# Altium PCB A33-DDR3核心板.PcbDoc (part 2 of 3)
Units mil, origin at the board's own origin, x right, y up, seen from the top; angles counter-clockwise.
Board outline 2370 x 2515 mil, 4 copper layers (TOP, GND02, PWR03, BOTTOM), stack 38.4 mil thick; 39 components, 64 nets, 546 pads, 403 vias.
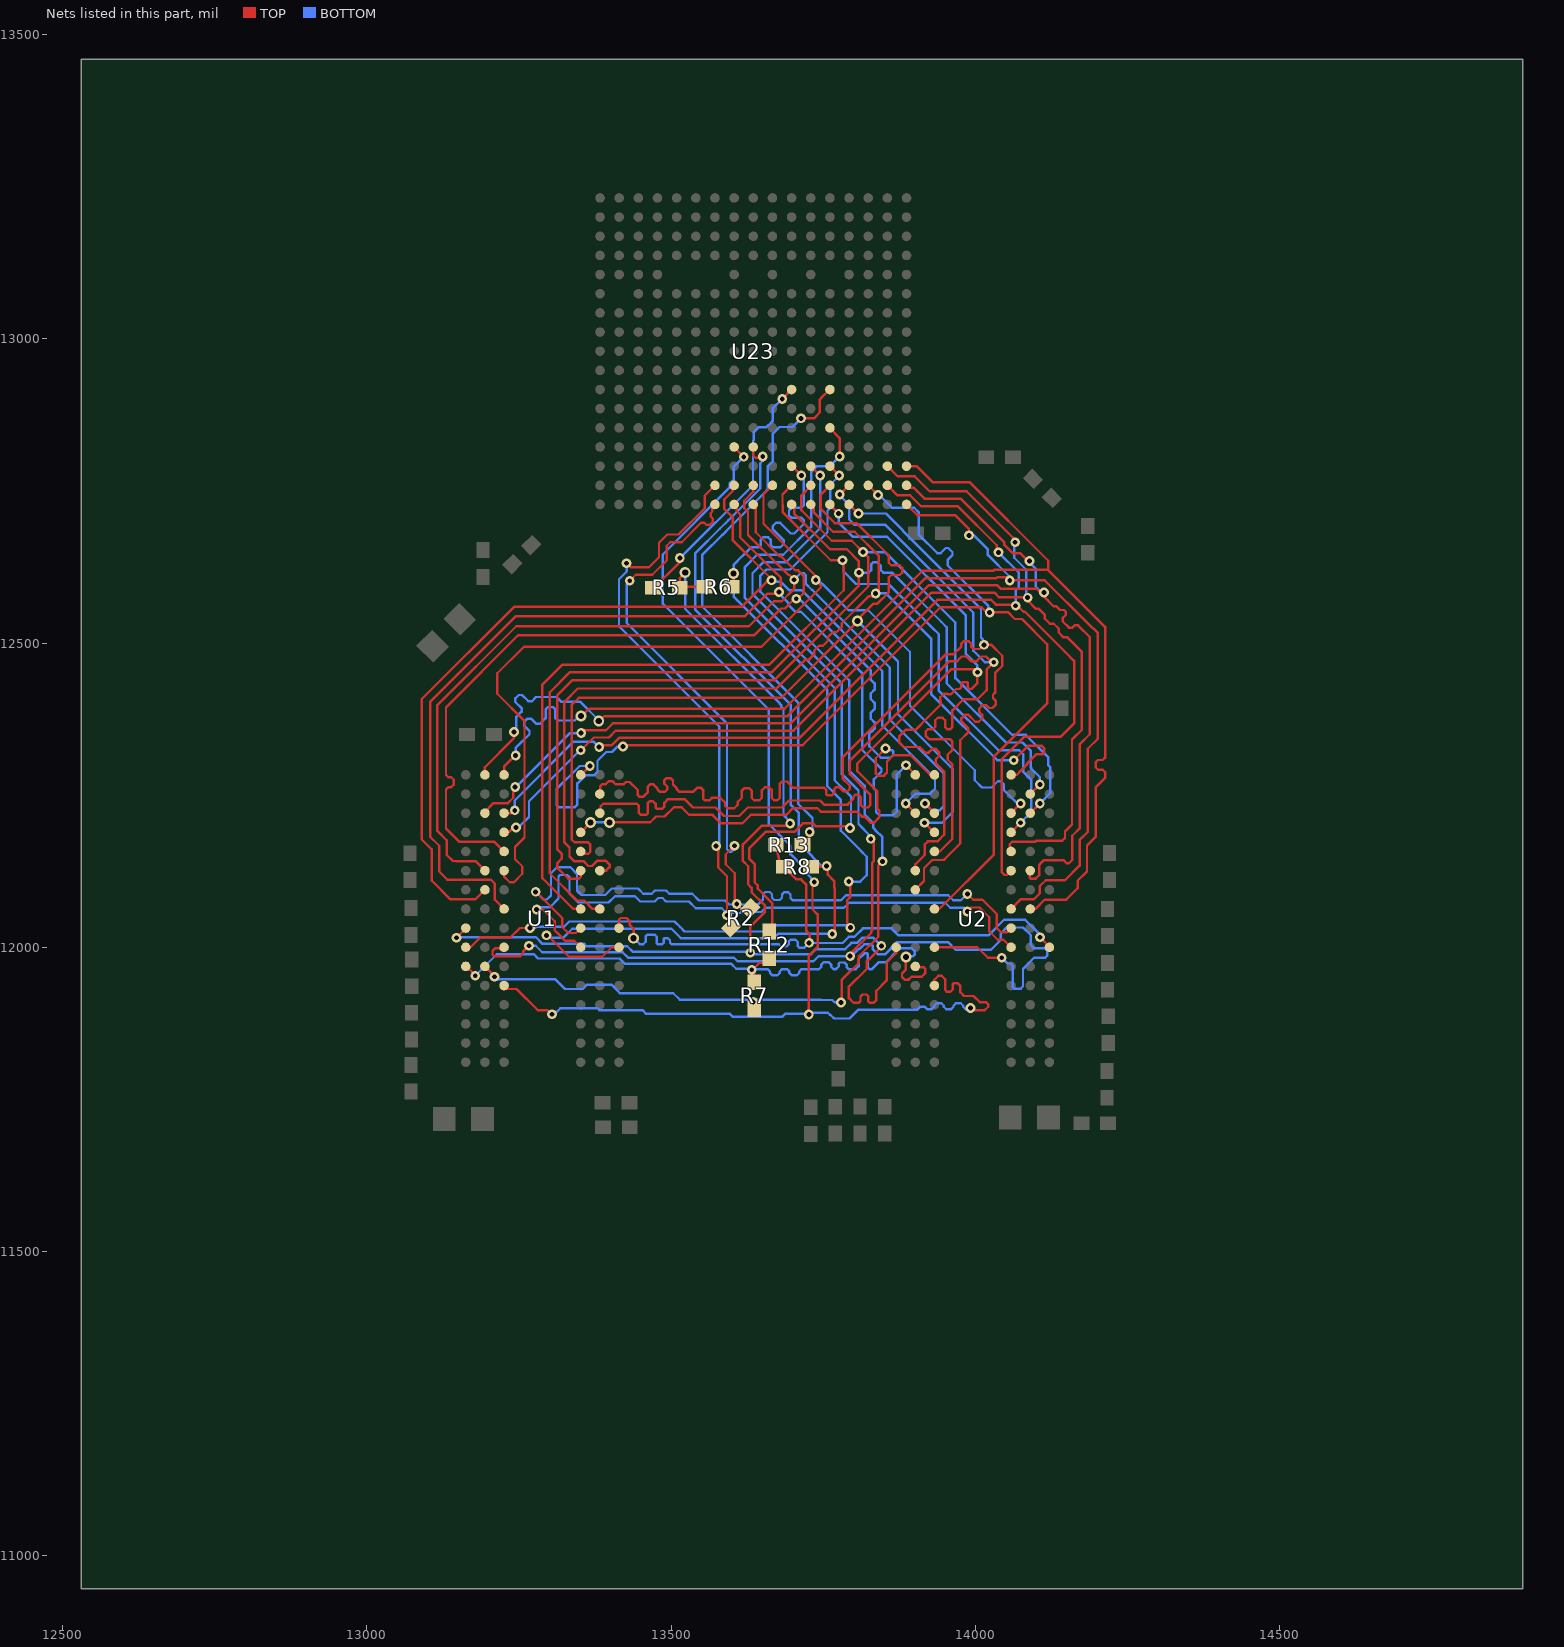
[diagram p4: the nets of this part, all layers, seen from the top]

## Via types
v1: diameter 16, hole 8, TOP to BOTTOM, 320 vias
v2: diameter 18, hole 10, TOP to BOTTOM, 83 vias

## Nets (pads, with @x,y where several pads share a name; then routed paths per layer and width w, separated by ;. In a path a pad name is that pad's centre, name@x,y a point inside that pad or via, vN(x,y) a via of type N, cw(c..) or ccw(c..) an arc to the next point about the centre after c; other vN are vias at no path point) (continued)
DBA2: U1.M3 U2.M3 U23.H4 | length 2134.1
  TOP w4: U1.M3@13225.38,11936.86 13231.01,11931.23 13246.06,11931.23 13280.9,11896.39 13296.38,11896.39 13303.1,11889.66 v1(13304.13,11889.66) ; U23.H4@13603.56,12822.31 13603.56,12821.96 v1(13619.44,12806.12) ; v1(13726.48,11889.19) 13726.48,11986.07 13740.93,12000.52 13740.93,12053.88 13732.44,12062.37 13732.44,12104.01 v1(13735.34,12106.91) ; U2.M3@13932.93,11936.85 13932.93,11946.4 13939.22,11952.69 13944.92,11952.69 13950.59,11947.01 13950.59,11929.56 13953.42,11926.73 13959.08,11926.73 13962.9,11930.55 13962.9,11938.95 13964.99,11941.04 13970.96,11941.04 13975.59,11936.41 13975.59,11925.8 13981.61,11919.78 13997.24,11919.78 14007.59,11909.43 14017.86,11909.43 14021.39,11905.89 14021.39,11902.09 14015.72,11896.41 13995.99,11896.41 v1(13992.24,11900.17)
  BOTTOM w4: v1(13304.13,11889.66) 13307.49,11889.66 13308.07,11890.24 13308.4,11890.24 13317.83,11899.67 13378.96,11899.67 13382.13,11896.5 13452.71,11896.5 13458.37,11890.84 13596.1,11890.84 13601.11,11885.83 13683.14,11885.83 13688.09,11890.78 13724.89,11890.78 v1(13726.48,11889.19) 13729.55,11892.27 13757.57,11892.27 13760.69,11889.15 13761.45,11889.15 13766.56,11884.04 13767.07,11884.04 13768.39,11882.72 13793.19,11882.72 13807.45,11896.98 13904.35,11896.98 13909.78,11902.41 13916.48,11902.41 13920.74,11898.15 13928.25,11898.15 13932.25,11902.15 13932.25,11903.78 13936.25,11907.78 13944.25,11907.78 13948.25,11903.78 13948.25,11902.15 13952.25,11898.15 13960.25,11898.15 13964.25,11902.15 13964.25,11903.78 13968.25,11907.78 13976.25,11907.78 13980.25,11903.78 13980.25,11902.15 13984.25,11898.15 13989.45,11898.15 13989.83,11897.77 v1(13992.24,11900.17) ; v1(13619.44,12806.12) 13618.64,12805.32 13618.45,12805.32 13603.08,12789.96 13603.08,12769.13 13596.09,12762.14 13596.09,12755.51 13486.19,12645.61 13486.19,12564.77 13658.8,12392.17 13658.8,12391.78 13660.79,12389.79 13660.79,12202 13677.88,12184.92 13677.88,12184.86 13696.04,12166.7 13696.04,12153.1 13723.7,12125.44 13723.7,12120.47 13735.09,12109.08 13735.09,12107.16 v1(13735.34,12106.91)
DCAS: U1.K3 U2.K3 U23.M3 | length 2302.2
  TOP w4: U1.K3@13225.37,11999.84 13223.94,11998.41 13211.05,11998.41 13206.36,11993.72 13206.36,11988.07 13209.25,11985.18 13251.73,11985.18 13256.67,11990.11 13256.67,11992.65 v1(13266.36,12002.34) ; U23.M3@13729.55,12790.81 v1(13745.02,12775.34) ; v1(13794.34,11985.25) 13794.34,11986.6 13796.84,11989.1 13796.84,11991.14 13829.35,12023.65 13829.35,12026.55 13830.47,12027.67 13830.47,12138.74 13832.82,12141.09 13832.82,12173.55 v1(13828.24,12178.13) ; U2.K3@13932.93,11999.84 14003.35,11999.84 14020.68,11982.52 v1(14043.58,11982.52)
  BOTTOM w4: v1(13266.36,12002.34) 13277.48,12002.34 13288.23,11991.6 13388.64,11991.6 13411.3,11991.59 13411.47,11991.43 13420.49,11991.43 13429.11,11982.81 13599.06,11982.81 13599.35,11982.52 13603.38,11982.52 13609.07,11976.83 13734.11,11976.83 13742.67,11985.39 13794.2,11985.39 v1(13794.34,11985.25) 13795.1,11986.01 13797.09,11986.01 13808.12,11997.04 13809.78,11997.04 13811.49,11998.75 ; v1(13745.02,12775.34) 13745.02,12688.8 13689.35,12633.13 13652.08,12633.13 13633.76,12614.82 13633.76,12580.54 13780.79,12433.51 13780.79,12284.53 13808.01,12257.32 13808.01,12202.24 13828.24,12182.01 v1(13828.24,12178.13) ; 13811.53,11998.75 13817.66,12004.88 13828.82,12004.88 13831.64,12002.05 13831.64,11996.39 13839.84,11988.19 13851.44,11988.19 13871.55,12008.3 13955.04,12008.3 13967.88,11995.46 14025.39,11995.46 14041.95,12012.01 14041.95,12022.62 14051.63,12032.31 14078.77,12032.31 14091.21,12019.86 14091.21,12003.7 14096.85,11998.06 14115.29,11998.06 14118.11,11995.23 14118.11,11985.88 14115.16,11982.92 14097.08,11982.92 14078.53,11964.37 14078.53,11935.67 14074.53,11931.67 14064.03,11931.67 14061.96,11933.73 14061.96,11968.93 14057.73,11973.17 14052.94,11973.17 v1(14043.58,11982.52)
DCK: R2.1 U1.J7 U2.J7 U23.G1 | length 1985.9
  TOP w3.7: v1(13277.32,12090.91) 13279.03,12089.2 13279.84,12089.2 13321.2,12047.83 13321.2,12032.63 13330.66,12023.17 13343.18,12023.17 U1.J7@13351.35,12031.34 ; v1(13431.99,12602.36) 13441.71,12612.08 13468.99,12612.08 13492.76,12635.84 13492.76,12649.74 13492.76,12659.82 13498.73,12665.79 13517.47,12665.79 13549.3,12697.62 13554.53,12697.62 13557.74,12694.41 13563.78,12694.41 13568.28,12698.91 13568.28,12704.8 13564.99,12708.09 13564.99,12713.32 13567.79,12716.12 13567.79,12723.55 U23.G1@13572.07,12727.82 ; v1(13604.08,12166.8) 13589.84,12152.56 13589.84,12136.28 13604.51,12121.61 13604.51,12074.41 v1(13607.79,12071.14) 13615.09,12063.83 R2.1@13629.84,12063.83 ; v1(13987.03,12087.52) 13996.63,12077.92 14012.08,12077.92 14035.53,12054.47 14035.53,12031.34 14042.2,12024.67 14052.24,12024.67 U2.J7@14058.91,12031.34
  BOTTOM w3.7: v1(13277.32,12090.91) 13290.04,12078.18 13295.56,12078.18 13302.44,12085.06 13302.44,12121.34 13312.31,12131.21 13334.55,12131.21 13345.31,12120.45 13345.31,12093.2 13352.72,12085.79 13391.76,12085.79 13402.38,12096.41 13445.61,12096.41 13454.26,12087.76 13468.02,12087.76 13473.4,12093.14 13491.54,12093.14 13496.92,12087.76 13534.59,12087.76 13545.69,12076.67 13588.51,12076.67 13595.14,12070.04 13606.69,12070.04 v1(13607.79,12071.14) 13608.74,12070.19 13642.91,12070.19 13651.22,12078.5 13651.22,12086.97 13654.92,12090.67 13662.32,12090.67 13666.02,12086.97 13666.02,12081.37 13669.72,12077.67 13678.42,12077.67 13682.12,12081.37 13682.12,12086.67 13685.62,12090.17 13692.62,12090.17 13696.12,12086.67 13696.12,12080.67 13699.62,12077.17 13779.16,12077.17 13787.51,12085.51 13955.68,12085.51 13964.02,12077.17 13976.68,12077.17 v1(13987.03,12087.52) ; v1(13431.99,12602.36) 13426.85,12597.22 13426.85,12532.81 13591.81,12367.85 13591.81,12160.93 13595.84,12156.9 13599.42,12156.9 13604.08,12161.57 v1(13604.08,12166.8)
DCKE: R8.2 U1.K9 U23.J4 | length 1618.8
  TOP w4: v1(13295.23,12019.47) 13297.09,12019.47 13332.4,11984.17 13386.8,11984.17 13402.47,11999.84 U1.K9@13414.35,11999.84 ; U23.J4@13635.06,12822.31 13635.06,12808.41 13638.78,12804.69 13648.62,12804.69 v1(13650.74,12806.81) ; R8.2@13729.74,12131.95 13752.55,12131.95 13754.19,12133.59 v1(13755.74,12133.59) 13755.74,12132.05 13757.39,12130.4 13757.39,12119.34 13767.93,12108.8 13767.93,12097.94 13769.2,12096.67 13769.2,12026.11 v1(13764.93,12021.84)
  BOTTOM w4: v1(13295.23,12019.47) 13297.09,12019.47 13300.77,12015.79 13323.06,12015.79 13337.47,12030.21 13500.53,12030.21 13515.84,12014.91 13669.24,12014.91 13676.68,12022.35 13752.88,12022.35 13753.4,12021.84 v1(13764.93,12021.84) ; v1(13650.74,12806.81) 13650.74,12799.64 13646.57,12795.47 13646.57,12754.36 13593.87,12701.66 13593.81,12701.66 13580.04,12687.89 13579.89,12687.89 13541.43,12649.43 13541.43,12649.28 13539.43,12647.28 13539.43,12555.21 13696.79,12397.85 13696.79,12233.59 13709.98,12220.41 13709.98,12181.21 13717.33,12173.86 13717.33,12163.68 13747.42,12133.59 v1(13755.74,12133.59)
DCKE1: R13.1 U23.N7 | length 941.9
  TOP w4: v1(13713.54,12869.42) 13734.7,12869.42 13744.42,12879.14 13744.42,12900.24 13746.48,12902.3 13746.48,12902.56 13760.71,12916.8 U23.N7@13761.04,12916.8 ; R13.1@13716.03,12168.45 13716.03,12170.54 13727.74,12182.26 v1(13727.74,12189.44)
  BOTTOM w4: v1(13713.54,12869.42) 13699.26,12855.14 13678.24,12855.14 13667.03,12843.94 13667.03,12798.52 13658.57,12790.06 13658.57,12752.27 13657.23,12750.94 13657.23,12750.88 13598.01,12691.66 13597.95,12691.66 13584.18,12677.89 13584.03,12677.89 13551.43,12645.29 13551.43,12559.66 13708.79,12402.3 13708.79,12235.74 13732.4,12212.13 13732.4,12194.1 v1(13727.74,12189.44)
DCKE1-D: R8.1 R13.2 U1.J9 U2.K9 | length 1049.5
  TOP w4: U1.J9@13414.35,12031.34 13414.35,12041.21 13414.53,12041.21 13414.53,12045.22 13417.27,12047.96 13426.52,12047.96 13432.11,12042.37 13432.11,12036.28 13438.58,12029.81 13438.58,12015.37 v2(13437.85,12014.64) ; R13.2@13672.03,12168.45 13678.83,12138.86 R8.1@13685.74,12131.95 13706.32,12111.37 13713.65,12111.37 13721.85,12103.17 13721.85,12100.6 13722.44,12100.01 13722.44,12026.45 13727.68,12021.21 v1@13727.68,12007.89 ; v1(13726.9,12007.11) v1@13727.68,12007.89 ; v1@13727.68,12007.13 v1@13727.68,12007.89 ; v1(14106.47,12016.23) 14121.9,12000.8 U2.K9@14121.9,11999.84
  BOTTOM w4: v2@13438.16,12014.33 v2(13437.85,12014.64) 13439.03,12014.64 13448.76,12004.91 13454.13,12004.91 13458.13,12008.91 13458.13,12017.79 13460.55,12020.21 13473.23,12020.21 13476.39,12017.06 13476.39,12006.65 13478.13,12004.91 13485.24,12004.91 13487.68,12007.35 13487.68,12013.81 13488.89,12015.02 13494.54,12015.02 13498.16,12011.4 13498.16,12007.62 13500.87,12004.91 13676.93,12004.91 13680.61,12001.23 13689.75,12001.23 13693.62,12005.1 13693.62,12009.39 13696.59,12012.35 13704.11,12012.35 13708.11,12008.35 13708.11,12001.77 13711.19,11998.7 13718.49,11998.7 v1(13726.9,12007.11) 13727.68,12007.11 13727.88,12006.91 13782.05,12006.91 13792.19,12017.04 13801.5,12017.04 13815.36,12030.91 13862.39,12030.91 13873.95,12019.35 14021.7,12019.35 14047.45,12045.09 14082.03,12045.09 14106.47,12020.66 v1(14106.47,12016.23)
DCKN: R2.2 U1.K7 U2.K7 U23.G2 | length 1975.6
  TOP w3.7: v1(13278.94,12061.92) 13289.44,12061.92 13308.7,12042.66 13308.7,12027.45 13313.02,12023.13 ; 13313.02,12023.12 13325.48,12010.67 13340.53,12010.67 U1.K7@13351.35,11999.84 ; v1(13426.47,12631.12) 13433.01,12624.58 13463.82,12624.58 13480.26,12641.02 13480.26,12665 13493.56,12678.29 13512.29,12678.29 13555.29,12721.3 13555.29,12742.55 U23.G2@13572.07,12759.32 ; v1(13574.07,12166.48) 13577.34,12163.2 13577.34,12131.1 13592.01,12116.43 v1@13592.01,12052.73 ; v1(13591.86,12052.57) v1@13592.01,12052.73 ; R2.2@13598.72,12032.72 13598.72,12043.84 13592.01,12050.55 v1@13592.01,12052.73 ; v1(13987.03,12058.67) 13993.78,12065.42 14006.9,12065.42 14023.03,12049.29 14023.03,12026.17 14037.03,12012.17 14046.59,12012.17 U2.K7@14058.91,11999.84
  BOTTOM w3.7: v1(13278.94,12061.92) 13282.7,12065.68 13300.74,12065.68 13314.94,12079.88 13314.94,12116.17 13317.48,12118.71 13329.37,12118.71 13332.81,12115.27 13332.81,12088.02 13347.54,12073.29 13396.93,12073.29 13407.55,12083.91 13440.43,12083.91 13449.08,12075.26 13473.2,12075.26 13478.58,12080.64 13486.36,12080.64 13491.74,12075.26 13529.41,12075.26 13540.51,12064.17 13583.34,12064.17 13591.86,12055.64 v1(13591.86,12052.57) ; v1(13426.47,12631.12) 13427.22,12630.37 13427.22,12617.6 13414.35,12604.73 13414.35,12527.63 13579.31,12362.67 13579.31,12171.72 v1(13574.07,12166.48) ; v1@13595.29,12057.54 13595.29,12050.09 13592.81,12052.57 v1(13591.86,12052.57) ; v1(13987.03,12058.67) 13981.03,12064.67 13958.84,12064.67 13950.5,12073.01 13792.68,12073.01 13784.34,12064.67 13655.07,12064.67 13648.09,12057.69 13615.34,12057.69 13613.94,12056.29 13595.58,12056.29 v1(13591.86,12052.57)
DCS: R7.2 U1.L2 U23.N3 | length 1741.2
  TOP w4: U1.L2@13193.87,11968.34 13209.51,11952.71 v1(13209.51,11951.28) ; R7.2@13633.76,11889.55 13633.76,11908.96 v1(13634.93,11910.12) ; U23.N3@13761.04,12790.81 v1(13776.51,12775.34) ; v1(13779.44,11909.15) 13780.27,11909.98 13780.27,11945.91 13808.5,11974.14 13808.5,11985.06 13840.47,12017.03 13840.47,12134.27 v1(13847.34,12141.14) ; v1(13634.93,11910.12) 13636.45,11908.59 R7.2@13636.45,11898.25 13634.93,11904.33 v1(13634.93,11910.12)
  BOTTOM w4: v1(13209.51,11951.28) 13213.83,11946.95 13309.9,11946.95 13325.59,11931.26 13354.67,11931.26 13361.8,11938.38 13401.79,11938.38 13415.87,11924.31 13503.55,11924.31 13514.16,11913.7 13629.02,11913.7 13632.6,11910.12 v1(13634.93,11910.12) 13638.51,11913.7 13745.82,11913.7 13746.33,11913.19 13764.93,11913.19 13768.98,11909.15 v1(13779.44,11909.15) ; v1(13776.51,12775.34) 13776.51,12775.07 13761.71,12760.27 13761.71,12722.22 13757.04,12717.55 13757.04,12682.09 13695.82,12620.87 13656.79,12620.87 13646.86,12610.95 13646.86,12584.41 13792.79,12438.48 13792.79,12290.5 13818.01,12265.28 13818.01,12218.18 13832.55,12203.65 13832.55,12195.97 13835.34,12193.17 13835.34,12192.93 13847.34,12180.93 v1(13847.34,12141.14)
DCS1: R12.1 U23.N5 | length 1180.1
  TOP w4: R12.1@13661.2,12025.64 13665.95,12030.4 13665.95,12072.59 13642.36,12096.17 13642.36,12101.63 13637.35,12106.65 13637.35,12136.61 13628.2,12145.75 13628.2,12162.43 13655.19,12189.42 13702.7,12189.42 13716.72,12203.44 13733.54,12203.44 13738.38,12198.6 13790.83,12198.6 13793.37,12196.05 v1(13794.24,12196.05) ; U23.N5@13761.04,12853.81 13761.04,12853.02 13777.09,12836.98 v1(13777.09,12806.57)
  BOTTOM w4: v1(13777.09,12806.57) 13761.34,12790.83 13739.73,12790.83 13730.03,12781.13 13730.03,12690.78 13684.38,12645.13 13641.42,12645.13 13621.22,12624.93 13621.22,12574.01 13768.79,12426.43 13768.79,12274.33 13795.68,12247.44 13795.68,12199.63 13794.24,12198.18 v1(13794.24,12196.05)
DCS1-D: R7.1 R12.2 U1.L1 U2.L2 | length 1074.1
  TOP w4: U1.L1@13162.38,11968.34 13163.88,11968.34 13177.21,11955.02 13177.21,11953.99 v1(13178.07,11953.12) ; v1@13633.76,11958.66 v1@13632.98,11959.44 ; v1@13635.28,11959.44 v1@13632.98,11959.44 ; R7.1@13636.45,11942.25 13636.45,11958.88 v1(13632.5,11962.83) ; R12.2@13661.2,11981.64 13654.11,11974.55 13645.74,11974.55 13635.82,11964.63 13634.3,11964.63 v1(13632.5,11962.83) ; v2(13886.06,11983.9) 13886.06,11963 13879.61,11956.55 13879.61,11950.9 13883.95,11946.56 13890.38,11946.56 13895.23,11951.41 13912.01,11951.41 13917.45,11956.85 13917.45,11964.76 13914.97,11967.24 13902.55,11967.24 U2.L2@13901.43,11968.35 ; v1(13632.5,11962.83) 13632.5,11959.92 v1@13632.98,11959.44
  BOTTOM w4: v1(13178.07,11953.12) 13213.23,11988.28 13274.55,11988.28 13281.39,11981.43 13415.32,11981.43 13424.23,11972.52 13599.24,11972.52 13607.13,11964.63 13626.92,11964.63 13631.63,11959.92 13632.5,11960.79 v1(13632.5,11962.83) 13633.56,11963.89 13658.56,11963.89 13662.56,11959.89 13662.56,11957.73 13666.56,11953.73 13674.56,11953.73 13678.56,11957.73 13678.56,11959.89 13682.56,11963.89 13690.56,11963.89 13694.56,11959.89 13694.56,11957.73 13698.56,11953.73 13706.56,11953.73 13710.56,11957.73 13710.56,11959.89 13714.56,11963.89 13742.98,11963.89 13746.98,11967.89 13746.98,11971.36 13750.98,11975.36 13758.98,11975.36 13762.98,11971.36 13762.98,11967.89 13766.98,11963.89 13771.09,11963.89 13771.09,11963.96 13775.59,11968.45 13775.59,11973.19 13777.18,11974.78 13785,11974.78 13788.96,11970.83 13788.96,11966.76 13791.84,11963.89 13803.51,11963.89 13808.39,11968.77 13808.39,11980.48 13817.69,11989.77 13822.28,11989.77 13823.34,11988.71 13823.34,11966.71 13826.16,11963.89 13829.96,11963.89 13841.51,11975.44 13853.73,11975.44 13863.19,11984.91 13863.19,11985.8 13875.69,11998.3 13895.68,11998.3 13900.35,11993.63 13900.35,11987.69 13897.73,11985.07 13887.22,11985.07 v2(13886.06,11983.9)
DODT: R6.1 U1.K1 U23.L3 | length 1769.5
  TOP w4: U1.K1@13162.38,11999.84 13169.98,11999.84 13186.37,12016.24 13236.12,12016.24 13251.35,12031.47 v1(13267.94,12031.47) ; R6.1@13599.1,12592.54 13599.1,12597.62 13602.71,12601.23 v2(13602.71,12614.21) ; U23.L3@13698.05,12790.81 13698.58,12790.81 v1(13714.05,12775.34) ; v1(13791.93,12107.88) 13794.61,12105.2 13794.61,12082.44 13789.51,12077.34 13789.51,12039.77 13794.61,12034.67 v1(13794.61,12032.13)
  BOTTOM w4: v1(13267.94,12031.47) 13276.57,12031.47 13278.57,12033.47 13323.76,12033.47 13332.5,12042.21 13505.83,12042.21 13514.97,12033.07 13522.29,12025.75 13663.11,12025.75 13673.5,12036.14 13790.59,12036.14 v1(13794.61,12032.13) ; v2@13602.71,12617.8 v2(13602.71,12614.21) 13602.71,12576.59 13756.79,12422.5 13756.79,12264.51 13779.2,12242.1 13779.2,12191.3 13812.07,12158.42 13812.07,12158.17 13821.58,12148.66 13821.58,12118.6 13810.87,12107.88 v1(13791.93,12107.88) ; v2@13602.74,12617.83 13602.74,12628.57 13617.84,12643.66 13617.89,12643.66 13631.36,12657.13 13643.54,12657.13 13647.54,12661.13 13647.54,12670.01 13651.54,12674.01 13659.54,12674.01 13663.54,12670.01 13663.54,12661.13 13667.54,12657.13 13679.41,12657.13 13685.42,12663.14 13685.42,12668.8 13666.91,12687.3 13666.91,12692.1 13672.57,12697.76 13679.08,12697.76 13696.73,12680.11 13702.39,12680.11 13718.03,12695.75 13718.03,12702.12 13714.03,12706.12 13697.79,12706.12 13693.79,12710.12 13693.79,12718.12 13697.79,12722.12 13714.03,12722.12 13718.03,12726.12 13718.03,12771.37 v1(13714.05,12775.34)
DODT1: R5.1 U23.L7 | length 428.9
  TOP w4: R5.1@13470.2,12590.8 13471.77,12590.8 13514.3,12633.32 v1(13514.3,12639.65) ; v1(13682.59,12901.34) U23.L7@13698.05,12916.8
  BOTTOM w4: v1(13514.3,12639.65) 13514.83,12639.65 13634.57,12759.39 13634.57,12832.11 13635.53,12833.07 13635.53,12846.06 13644.37,12854.91 13656.81,12854.91 13665.6,12863.7 13666.84,12864.95 13666.84,12885.59 v1(13682.59,12901.34)
DODT1-D: R5.2 R6.2 U1.J1 U2.K1 | length 1882.2
  TOP w4: v1(13147.2,12015.6) 13162.38,12030.78 U1.J1@13162.38,12031.34 ; v2(13523.16,12615.8) 13514.2,12606.83 R5.2@13514.2,12590.8 13515.94,12592.54 R6.2@13555.1,12592.54 ; v1(13630.26,11990.91) 13630.26,12033.85 13654.26,12057.85 13654.26,12068.41 13632.36,12090.3 13632.36,12097.49 13626.77,12103.09 13626.77,12133.05 13618.08,12141.73 13618.08,12168.92 13648.58,12199.42 13691.63,12199.42 v1(13695.63,12203.42) ; v1(13845.64,12002.19) 13845.64,12000.6 13821.74,11976.69 13821.74,11964.51 13792.32,11935.09 13792.32,11916.14 13800.15,11908.31 13808.25,11908.31 13811.35,11911.41 13811.35,11918.93 13814.62,11922.2 13821.31,11922.2 13824.18,11919.33 13824.18,11910.84 13826.72,11908.31 13832.84,11908.31 13837.42,11912.88 13837.42,11928.4 13854.28,11945.27 13854.28,11974.44 13869.94,11990.1 U2.K1@13869.94,11999.84
  TOP w5.2: R6.2@13555.1,12592.54 R6.2@13555.1,12597.06
  BOTTOM w4: v1(13147.2,12015.6) 13147.95,12016.35 13277.62,12016.35 13288.5,12005.47 13301.03,12005.47 13301.35,12005.79 13357.11,12005.79 13361.3,12001.6 13392.78,12001.6 13415.44,12001.59 13415.61,12001.43 13427.83,12001.43 13436.46,11992.81 13625.7,11992.81 13627.21,11991.3 13629.87,11991.3 v1(13630.26,11990.91) 13632.47,11988.7 13730.1,11988.7 13738.32,11996.91 13786.19,11996.91 13796.33,12007.04 13805.64,12007.04 13813.75,12015.16 13832.68,12015.16 v1(13845.64,12002.19) ; v2(13523.16,12615.8) 13523.16,12606.36 13522.94,12606.14 13522.94,12556.31 13678.79,12400.45 13678.79,12400.07 13680.79,12398.07 13680.79,12395.83 13684.79,12391.83 13684.79,12217.01 13695.63,12206.17 v1(13695.63,12203.42)
DQ0: U1.F8 U2.A7 U23.M1 | length 1703.7
  TOP w4: U1.F8@13382.85,12125.82 13393.12,12125.82 13398.82,12131.52 13398.82,12135.82 13392.32,12142.32 13379.12,12142.32 13370.2,12133.4 13363.85,12133.4 13355.84,12141.42 13340.61,12141.42 13332.89,12149.14 13332.89,12163.87 13324.45,12172.31 13324.45,12403.07 13346.6,12425.22 13673.09,12425.22 13720.76,12472.89 13726.93,12472.89 13735.16,12481.11 13735.16,12481.63 13735.16,12487.29 13743.38,12495.52 13743.9,12495.52 13749.56,12495.52 13757.79,12503.74 13757.79,12504.26 13757.79,12509.92 13766.01,12518.14 13766.53,12518.14 13772.19,12518.14 13780.41,12526.37 13780.41,12526.89 13780.41,12532.55 13824.62,12576.76 13831.45,12576.76 v1(13836.3,12581.6) 13841.15,12586.45 13841.15,12643.73 13801.87,12683.01 13766.3,12683.01 13734.17,12715.15 13734.17,12723.2 U23.M1@13729.55,12727.82 ; U2.A7@14058.91,12283.31 14068.12,12283.31 14074.61,12289.79 14074.61,12289.85 14085.16,12300.41 14085.16,12301.73 14100.75,12317.32 14110.77,12317.32 14113.23,12319.78 14113.23,12327.09 14109.52,12330.8 14087.33,12330.8 14084.5,12327.97 14083.96,12327.97 v1(14063.22,12307.24)
  BOTTOM w4: v1(13836.3,12581.6) 13853.37,12581.6 13927.52,12507.45 13927.52,12416.14 14036.43,12307.24 v1(14063.22,12307.24)
DQ1: U1.F7 U2.C8 U23.M2 | length 1774.7
  TOP w4: U1.F7@13351.35,12125.82 13351.35,12115.56 13348.28,12112.48 13331.18,12112.48 13312.45,12131.21 13312.45,12137.85 13319.94,12145.34 13319.94,12153.85 13312.45,12161.34 13312.45,12413.88 13337.75,12439.18 13670.08,12439.18 13824.3,12593.4 13824.3,12640.74 v1(13815.47,12649.57) 13796.87,12668.17 13764.17,12668.17 13714.12,12718.22 13714.12,12742.53 13729.55,12757.96 U23.M2@13729.55,12759.32 ; U2.C8@14090.41,12220.32 v1@14106.15,12236.06
  BOTTOM w4: v1(13815.47,12649.57) 13851.33,12649.57 13950.25,12550.66 13965.87,12535.03 13967.35,12533.55 13967.35,12442.41 14060.49,12349.27 14082.86,12349.27 14119.71,12312.41 14119.71,12299.29 14123.07,12295.93 14123.07,12252.98 v1(14106.15,12236.06)
DQ2: U1.H8 U2.B8 U23.L1 | length 1745.7
  TOP w4: U1.H8@13382.85,12062.83 13370.98,12062.83 13357.1,12076.71 13345.37,12076.71 13300.45,12121.64 13300.45,12418.85 13333.78,12452.18 13666.11,12452.18 13808.8,12594.88 v1(13808.8,12615.74) 13808.8,12634.33 13789.03,12654.1 13761.27,12654.1 13702.12,12713.25 13702.12,12723.75 U23.L1@13698.05,12727.82 ; U2.B8@14090.41,12251.81 v1@14106.15,12267.55
  BOTTOM w4: v1(13808.8,12615.74) 13824.89,12615.74 13828.89,12619.74 13828.89,12629.3 13832.75,12633.16 13838.21,12633.16 13844.89,12626.48 13844.89,12619.74 13848.89,12615.74 13863.33,12615.74 13928.42,12550.66 13944.04,12535.03 13953.22,12525.85 13953.22,12433.69 14050.45,12336.47 14077.56,12336.47 14091.48,12322.54 14091.48,12295.08 14091.71,12294.86 14091.71,12293.73 14106.15,12279.29 v1(14106.15,12267.55)
DQ3: U1.H7 U2.D7 U23.L2 | length 1834.1
  TOP w4: U1.H7@13351.35,12062.83 13339.01,12062.83 13288.45,12113.4 13288.45,12431.89 13320.74,12464.18 13661.14,12464.18 13783.76,12586.81 13783.76,12633.38 13781.79,12635.35 v1(13781.79,12636.01) 13762.39,12636.01 13683.17,12715.23 13683.17,12726.81 13683.11,12726.87 13683.11,12744.39 U23.L2@13698.04,12759.32 ; U2.D7@14058.91,12188.82 v1(14074.66,12204.56)
  BOTTOM w4: v1(13781.79,12636.01) 13783.78,12634.03 13783.78,12617.5 13804.18,12597.1 13857.57,12597.1 13904.01,12550.66 13929.14,12525.53 13940.32,12514.35 13940.32,12421.44 14038.1,12323.67 14072.25,12323.67 14078.68,12317.23 14078.68,12288.65 14091.74,12275.59 14091.74,12221.65 v1(14074.66,12204.56)
DQ4: U1.E3 U2.A3 U23.J1 | length 1741.7
  TOP w4: U1.E3@13225.37,12157.32 13209.67,12173.02 13152,12173.02 13129.86,12195.15 13129.86,12259.26 13133.86,12263.26 13138.6,12263.26 13142.6,12267.26 13142.6,12275.26 13138.6,12279.26 13133.86,12279.26 13129.86,12283.26 13129.86,12394.24 13248.65,12513.02 13636.78,12513.02 13680.53,12556.78 13686.94,12556.78 13701.37,12571.21 13704.2,12571.21 v1(13705.75,12572.76) 13708.64,12572.76 13717.73,12581.85 13717.73,12610.47 13708.65,12619.55 13704.13,12619.55 13681.13,12642.55 13678.68,12642.55 13639.18,12682.05 13639.18,12720.76 13635.06,12724.89 U23.J1@13635.06,12727.82 ; v1(13852.35,12326.5) 13836.5,12310.65 13836.5,12285.42 13839.84,12282.08 13843.01,12282.08 13850.07,12282.08 13854.94,12286.95 13854.94,12305.45 13865.1,12315.62 13893.6,12315.62 13925.91,12283.31 U2.A3@13932.93,12283.31
  BOTTOM w4: v1(13705.75,12572.76) 13708.75,12569.76 13713.3,12569.76 13828.49,12454.58 13828.49,12439.54 13834.47,12433.55 13834.47,12423.54 13828.49,12417.55 13828.49,12407.54 13834.47,12401.55 13834.47,12391.54 13828.49,12385.55 13828.49,12375.54 13834.47,12369.55 13834.47,12359.34 13829.97,12354.84 13829.21,12354.84 13826.03,12351.67 13826.03,12330.26 13844.88,12311.42 13860.7,12311.42 13865.22,12315.94 13865.22,12321.9 13863.37,12323.75 13855.11,12323.75 v1(13852.35,12326.5)
DQ5: U1.F2 U2.C3 U23.J2 | length 1763.2
  TOP w4: U1.F2@13193.87,12125.82 13178.12,12141.58 13146.83,12141.58 13146.74,12141.66 13141.29,12141.66 13131.01,12151.94 13131.01,12175.76 13115.76,12191 13115.76,12397.9 13245.43,12527.56 13627.83,12527.56 13669.05,12568.78 13681.97,12568.78 13702.23,12589.05 v1(13702.23,12604.06) 13694.48,12611.81 13692.99,12611.81 13674.25,12630.55 13673.71,12630.55 13626.39,12677.88 13626.39,12715.46 13620.18,12721.66 13620.18,12733.98 13635.06,12748.86 U23.J2@13635.06,12759.32 ; v1(13917.19,12236.06) U2.C3@13932.93,12220.32
  BOTTOM w4: v1(13702.23,12604.06) 13712.95,12614.77 13718.44,12614.77 13721.74,12611.47 13721.74,12596.88 13731.11,12587.51 13731.76,12587.51 13859.43,12459.83 13859.43,12374.22 13948.36,12285.29 13948.36,12232.2 13941.01,12224.85 13928.4,12224.85 v1(13917.19,12236.06)
DQ6: U1.H3 U2.A2 U23.H1 | length 1845.4
  TOP w4: U1.H3@13225.37,12062.83 13210.31,12077.9 13210.31,12104.37 13203.85,12110.83 13138.61,12110.83 13138.5,12110.94 13132.3,12110.94 13118.76,12124.47 13118.76,12166.63 13103.76,12181.63 13103.76,12403.31 13244.29,12543.84 13620.85,12543.84 13657.79,12580.78 13672.08,12580.78 13675.14,12583.83 v1(13677.22,12583.83) 13678.17,12584.78 13678.17,12587.53 13680.45,12589.81 13680.45,12607.38 13669.28,12618.55 13668.74,12618.55 13613.56,12673.73 13613.56,12711.31 13608.18,12716.69 13608.18,12723.2 U23.H1@13603.56,12727.82 ; v1(13886.31,12299.1) 13901.43,12283.98 U2.A2@13901.43,12283.31
  BOTTOM w4: v1(13677.22,12583.83) 13678.17,12582.89 13678.17,12580.78 13692.3,12566.65 13692.3,12563.34 13703.87,12551.77 13713.19,12551.77 13814.03,12450.93 13814.03,12324.68 13845.91,12292.8 13845.91,12288.63 13833.37,12276.09 13833.37,12260.86 13837.54,12256.7 13837.54,12221.58 13842.09,12217.03 13865.27,12217.03 13870.98,12222.74 13870.98,12257.34 13871.13,12257.49 13871.13,12283.93 v1(13886.31,12299.1)
DQ7: U1.G2 U2.C2 U23.H2 | length 1815.5
  TOP w4: U1.G2@13193.87,12094.33 13178.07,12078.53 13155.84,12078.53 13137.3,12078.54 13106.44,12109.39 13106.44,12160.84 13089.97,12177.31 13089.97,12407.74 13241.78,12559.55 13615.63,12559.55 13660,12603.93 v1@13662.23,12603.93 ; U23.H2@13603.56,12759.32 13601.34,12757.1 13601.34,12750.1 13587.33,12736.09 13587.33,12720.58 13601.48,12706.43 13601.48,12668.84 13662.23,12608.08 v1@13662.23,12603.93 ; v1(13664.96,12603.06) 13663.11,12603.06 v1@13662.23,12603.93 ; v1(13885.69,12236.06) U2.C2@13901.43,12220.32
  BOTTOM w4: v1(13664.96,12603.06) 13667.01,12601 13679.85,12601 13693.77,12587.09 13714.07,12587.09 13847.43,12453.73 13847.43,12363.98 13933.79,12277.62 13933.79,12260.56 13925.79,12252.56 13902.19,12252.56 v1(13885.69,12236.06)
DQ8: U1.A3 U2.H8 U23.U3 | length 2125.6
  TOP w4: U1.A3@13225.37,12283.31 13225.37,12296.95 13243.49,12315.07 v1(13244.35,12315.07) ; v2(13351.77,12380.26) 13353.47,12380.26 13365.16,12391.96 13686.48,12391.96 13913.34,12618.82 14029.37,12618.82 14030.78,12620.23 14119.84,12620.23 ; U23.U3@13887.03,12790.81 13903.43,12790.81 13929.69,12764.55 13990.69,12764.55 14119.97,12635.27 14119.97,12620.35 14119.84,12620.23 ; U2.H8@14087.69,12062.84 U2.H8@14090.41,12062.84 14098.98,12062.84 14114.35,12078.21 14149.63,12078.21 14168.57,12097.16 14168.57,12109.33 14183.73,12124.48 14183.73,12167.05 14198.45,12181.78 14198.45,12263.17 14213.53,12278.25 14213.53,12287.75 14209.53,12291.75 14201.98,12291.75 14197.98,12295.75 14197.98,12303.75 14201.98,12307.75 14209.53,12307.75 14213.53,12311.75 14213.53,12526.54 14119.84,12620.23
  BOTTOM w4: v1(13244.35,12315.07) 13244.35,12327.27 13267.12,12350.03 13267.12,12355.69 13258.25,12364.56 13258.25,12370.22 13263.91,12375.87 13269.56,12375.87 13278.43,12367 13284.09,12367 13293.75,12376.66 13293.75,12390.8 13297.75,12394.8 13305.75,12394.8 13309.75,12390.8 13309.75,12376.66 13313.75,12372.66 13341.55,12372.66 13347.13,12378.24 13349.75,12378.24 v2(13351.77,12380.26)
DQ9: U1.A2 U2.H7 U23.U1 | length 2055.5
  TOP w4: U1.A2@13193.87,12283.31 13193.87,12295.8 13241.73,12343.66 v1(13241.73,12353.66) ; v2(13381.04,12371.67) 13381.8,12371.67 13390.09,12379.96 13691.45,12379.96 13918.31,12606.82 14034.34,12606.82 14035.71,12608.19 14051.32,12608.19 v1(14056.6,12602.91) 14114.3,12602.91 14185.11,12532.09 14185.65,12532.09 14201.53,12516.21 14201.53,12342.7 14184.94,12326.11 14184.94,12189.64 14171.53,12176.23 14171.53,12134.12 14147.54,12110.13 14115.94,12110.13 14106.1,12100.29 14106.1,12088.39 14096.25,12078.53 14074.61,12078.53 U2.H7@14058.91,12062.84 ; U23.U1@13887.03,12727.82 13904.6,12710.25 13966.77,12710.25 13989.73,12687.28 v1(13989.73,12677.03)
  BOTTOM w4: v1(13241.73,12353.66) 13245.46,12357.39 13245.46,12378.68 13254.09,12387.31 13254.09,12392.97 13243.76,12403.3 13243.76,12408.95 13249.41,12414.61 13255.07,12414.61 13265.4,12404.28 13271.06,12404.28 13278.08,12411.29 13311.81,12411.29 13319.85,12403.26 13350.94,12403.26 13381.04,12373.16 v2(13381.04,12371.67) ; v1(13989.73,12677.03) 13997.8,12677.03 14020.85,12653.98 14020.85,12644.64 14056.6,12608.89 v1(14056.6,12602.91)
DQ10: U1.C2 U2.F8 U23.U2 | length 2025.6
  TOP w4: U1.C2@13193.87,12220.31 13193.87,12222.66 13208.03,12236.81 13231.59,12236.81 13240.37,12245.59 13240.37,12259.99 v1(13243.62,12263.24) ; v1(13352.03,12351.96) 13352.56,12351.96 13357.28,12356.67 13392.78,12356.67 13404.07,12367.96 13696.42,12367.96 13923.28,12594.82 14036.32,12594.82 14042.24,12588.91 14101.02,12588.91 14106.75,12583.17 v1(14113.09,12583.17) 14113.09,12579.94 14114.52,12578.51 14114.52,12574.85 14129.02,12560.35 14133.53,12560.35 14139.56,12554.32 14145.89,12554.32 14148.69,12551.52 14148.69,12546.15 14143.89,12541.35 14143.89,12535.42 14153.92,12525.39 14159.57,12525.39 14163.23,12529.04 14169.08,12529.04 14188.33,12509.8 14188.33,12350.11 14171.95,12333.73 14171.95,12195.68 14159.53,12183.26 14159.53,12143.41 14154.15,12138.02 14149.97,12138.02 14144.79,12143.21 14112.99,12143.21 14104.87,12135.08 14104.87,12118.31 14099.28,12112.72 14091.18,12112.72 14089.29,12114.61 14089.29,12124.72 U2.F8@14090.41,12125.83 ; U23.U2@13887.03,12759.32 13890.85,12755.5 13898.49,12755.5 13916.52,12737.47 13975.82,12737.47 14047.35,12665.94 14047.35,12662.03 14061.89,12647.5 14074.15,12647.5 14086.84,12634.8 v1(14089.37,12634.8)
  BOTTOM w4: v1(13243.62,12263.24) 13245.19,12263.24 13333.91,12351.96 v1(13352.03,12351.96) ; v1(14089.37,12634.8) 14089.37,12632.28 14099.11,12622.54 14099.11,12593.4 14109.34,12583.17 v1(14113.09,12583.17)
DQ11: U1.C3 U2.F7 U23.T2 | length 1930.2
  TOP w4: U1.C3@13225.37,12220.31 13236.05,12220.31 13240.68,12224.94 v1(13242.85,12224.94) ; v1(13381.62,12329.01) 13382.02,12329.01 13383.41,12330.4 13384.79,12330.4 13386.49,12332.1 13402.64,12332.1 13414.49,12343.96 13710.88,12343.96 13937.74,12570.82 14026.38,12570.82 14033.95,12563.26 14064.14,12563.26 14066.14,12561.26 v1(14066.41,12561.26) 14069.59,12561.26 14079.34,12551.5 14081.55,12551.5 14147.06,12485.99 14147.22,12485.99 14162.43,12470.78 14162.43,12367.82 14140.25,12345.65 14080.04,12345.65 14043.75,12309.36 14043.75,12123.17 14048.25,12118.67 14051.76,12118.67 U2.F7@14058.91,12125.83 ; U23.T2@13855.53,12759.32 13872.15,12742.7 13893.19,12742.7 13911.22,12724.67 13971.54,12724.67 14035.35,12660.85 14035.35,12652.05 v1(14038.32,12649.09)
  BOTTOM w4: v1(13242.85,12224.94) 13242.85,12241.16 13339.65,12337.96 13372.68,12337.96 v1(13381.62,12329.01) ; v1(14038.32,12649.09) 14071.86,12615.54 14071.86,12591.61 14066.41,12586.16 v1(14066.41,12561.26)
DQ12: U1.A7 U2.H3 U23.R2 | length 1980.1
  TOP w4: U1.A7@13351.35,12283.31 13351.83,12283.31 v1@13366.34,12297.81 ; v1(13420.9,12329.89) 13420.96,12329.89 13423.03,12331.96 13716.13,12331.96 13801,12416.83 13801,12417.12 13942.71,12558.82 14010.37,12558.82 14019.04,12550.15 v1(14023.68,12550.15) ; U23.R2@13824.04,12759.32 13840.02,12743.34 v1(13840.02,12743.24) ; U2.H3@13932.93,12062.84 13940.9,12062.84 14030.71,12152.65 14030.71,12313.3 14118.12,12400.7 14118.12,12497.96 14076.58,12539.5 14064.99,12539.5 14053.75,12550.74 14029.07,12550.74 14028.49,12550.15 v1(14023.68,12550.15) ; v1@14024.56,12551.03 v1(14023.68,12550.15)
  BOTTOM w4: v1(13366.36,12297.81) 13364.74,12297.81 13364.65,12297.9 13349.81,12297.9 13311.74,12259.83 13311.74,12233.75 13315.72,12229.78 13341.19,12229.78 13345.78,12234.37 13345.78,12269.27 13358.96,12282.45 13373.07,12282.45 13378.98,12288.36 13378.98,12306.58 13393.26,12320.85 13402.86,12320.85 13411.91,12329.89 v1(13420.9,12329.89) ; v1(13840.02,12743.24) 13842.21,12743.24 13863,12722.45 13899.65,12722.45 13906.87,12715.23 13906.87,12678.57 13937.58,12647.87 13943.24,12647.87 13951.59,12656.22 13955.51,12656.22 13962.56,12649.18 13962.56,12644.56 13954.55,12636.55 13954.55,12627.81 14021.49,12560.87 14021.49,12552.35 v1(14023.68,12550.15)
DQ13: U1.B8 U2.G2 U23.P1 | length 1948
  TOP w4: U1.B8@13382.85,12251.81 13383.23,12252.18 13383.23,12264.43 13386.6,12267.81 13392.41,12267.81 13397.64,12273.05 13403.33,12273.05 13408.57,12267.81 13421.76,12267.81 13425.54,12271.58 13431.69,12271.58 13445.36,12257.91 13445.36,12249.9 13448.19,12247.07 13453.85,12247.07 13461.25,12254.47 13461.25,12263.56 13465.25,12267.56 13470.78,12267.56 13477.58,12260.76 13477.58,12259.31 13481.58,12255.31 13489.58,12255.31 13493.58,12259.31 13493.58,12263.86 13488.81,12268.63 13488.81,12274.69 13492.13,12278 13499.15,12278 13503.05,12274.1 13503.05,12267.29 13509.58,12260.76 13509.58,12259.31 13513.58,12255.31 13536.14,12255.31 13542.64,12261.81 13549.27,12261.81 13552.53,12258.56 13552.53,12244.19 13555.13,12241.6 13563.24,12241.6 13566.96,12245.32 13580.85,12245.32 13588.57,12237.6 13588.57,12232.41 13592.57,12228.41 13603.83,12228.41 13609.79,12234.37 13609.79,12239.05 13616.33,12245.6 13616.33,12257.59 13620.33,12261.59 13628.33,12261.59 13632.33,12257.59 13632.33,12245.6 13636.33,12241.6 13645.11,12241.6 13649.11,12245.6 13649.11,12258.04 13653.85,12262.78 13661.16,12262.78 13665.11,12258.83 13665.11,12245.6 13669.11,12241.6 13674.85,12241.6 13678.85,12245.6 13678.85,12268.83 13682.41,12272.4 13690.41,12272.4 13700.83,12261.98 13745.81,12261.98 13745.93,12261.86 13751.59,12261.86 13754.95,12258.5 13754.95,12251.66 13756.93,12249.68 13764.32,12249.68 13768.17,12253.53 13768.17,12259.94 13771,12262.77 13776.66,12262.77 13783.42,12256.01 13789.58,12256.01 13793.59,12260.01 13793.59,12265.67 13781.94,12277.32 13781.94,12311.94 13951.76,12481.76 13964.64,12481.76 13977.09,12494.21 13977.09,12499.25 13981.09,12503.25 13989.09,12503.25 13993.09,12499.25 13993.09,12494.21 13997.09,12490.21 14007.49,12490.21 v1(14014.32,12497.04) 14026.48,12497.04 14044.47,12479.05 14044.47,12462.55 14032.56,12450.64 14032.56,12418.43 14029.18,12415.04 14029.18,12409.39 14034.04,12404.53 14034.04,12398.87 14028.38,12393.22 14022.72,12393.22 14017.87,12398.07 14012.21,12398.07 14006.55,12392.42 14006.55,12386.76 14011.41,12381.9 14011.41,12376.25 14005.75,12370.59 14000.1,12370.59 13988.89,12381.79 13982.89,12381.79 13977.23,12376.14 13977.23,12370.82 13988.78,12359.28 13988.78,12353.62 13975.37,12340.21 13975.37,12170.48 13951.87,12146.98 13948.34,12143.45 13947.45,12143.45 13947.33,12143.33 13929.39,12143.33 13915.71,12129.65 13915.71,12108.61 U2.G2@13901.43,12094.33 ; U23.P1@13792.54,12727.82 13807.44,12712.93 v1(13808,12712.93)
  BOTTOM w4: v1(13808,12712.93) 13853.08,12712.93 13881.21,12684.8 13881.21,12684.18 13999.65,12565.74 14009.49,12555.9 14009.49,12508.93 14012.76,12505.66 14012.76,12498.6 v1(14014.32,12497.04)
DQ14: U1.C8 U2.E3 U23.P2 | length 1891.1
  TOP w4: U1.C8@13382.85,12220.31 13383.93,12221.4 13383.93,12231.17 13388.5,12235.73 13443.62,12235.73 13446.99,12232.36 13446.99,12220.85 13450.25,12217.6 13459.04,12217.6 13461.71,12220.26 13461.71,12237.2 13464.51,12240 13470.17,12240 13474.51,12235.66 13474.51,12229.27 13476.51,12227.27 13484.86,12227.27 13488.84,12231.24 13488.84,12237.2 13494.95,12243.31 13522.12,12243.31 13535.84,12229.6 13573.21,12229.6 13587.2,12215.6 13611.89,12215.6 13625.89,12229.6 13682.09,12229.6 13693.66,12241.16 13744.68,12241.16 13751.41,12234.44 13790.07,12234.44 13799.32,12243.69 13799.32,12246.8 13803.22,12250.71 13807.83,12250.71 13811.83,12246.71 13811.83,12233.6 13815.83,12229.6 13823.45,12229.6 13827.19,12233.34 13827.19,12251.11 13793.94,12284.37 13793.94,12306.97 13956.73,12469.76 13969.78,12469.76 13973.78,12473.76 13973.78,12473.93 13977.78,12477.93 13985.78,12477.93 13989.78,12473.93 13989.78,12473.76 13993.78,12469.76 14001.78,12469.76 14005.78,12473.76 14005.78,12473.93 14009.78,12477.93 14017.78,12477.93 14021.78,12473.93 14021.78,12473.76 14025.78,12469.76 14029.05,12469.76 v1(14030.47,12468.35) 14018.73,12456.61 14018.73,12422.46 14003.82,12407.55 13980.81,12407.55 13962.43,12389.17 13962.43,12362.02 13958.43,12358.02 13954.34,12358.02 13950.34,12362.02 13950.34,12373.06 13946.34,12377.06 13938.34,12377.06 13934.34,12373.06 13934.34,12362.02 13930.34,12358.02 13921.86,12358.02 13918.9,12355.06 13918.9,12347.06 13923.94,12342.02 13958.43,12342.02 13962.43,12338.02 13962.43,12324.09 13954.83,12316.49 13954.83,12308.09 13962.43,12300.49 13962.43,12178.23 13941.53,12157.33 U2.E3@13932.93,12157.33 ; v1@13778.31,12745.45 v1(13777.25,12744.39) 13777.61,12744.39 U23.P2@13792.54,12759.32
  BOTTOM w4: v1(13777.25,12744.39) 13777.25,12742.71 13792.51,12727.45 13792.51,12703.47 13801.68,12694.31 13852.46,12694.31 13996.68,12550.09 13996.68,12487.53 14015.87,12468.35 v1(14030.47,12468.35)
DQ15: U1.D7 U2.F2 U23.N1 | length 1874.4
  TOP w4: v2(13367.5,12204.73) 13351.59,12188.82 U1.D7@13351.35,12188.82 v2@13367.97,12205.43 ; v2(13398.58,12205.11) 13398.78,12205.31 13420.56,12205.31 13420.68,12205.43 13465.6,12205.43 13474.99,12214.82 13489.39,12214.82 13504.68,12230.12 13517.31,12230.12 13529.83,12217.6 13568.24,12217.6 13582.23,12203.6 13616.87,12203.6 13630.86,12217.6 13689.28,12217.6 13700.29,12228.61 13740.22,12228.61 13746.23,12222.6 13746.44,12222.44 13806.02,12222.44 13813.73,12214.72 13817.7,12214.72 13827.79,12204.63 13833.45,12204.63 13842.62,12213.8 13842.62,12224.22 13839.19,12227.65 13839.19,12256.09 13805.94,12289.34 13805.94,12302 13961.17,12457.23 13998.24,12457.23 v1(14003.53,12451.94) 14003.53,12434.05 13993.89,12424.41 13990.15,12424.41 13987.89,12426.67 13987.89,12434.34 13986.38,12435.85 13980.07,12435.85 13976.97,12432.75 13976.97,12427.18 13974.2,12424.41 13968.79,12424.41 13960.13,12415.76 13954.48,12415.76 13953.79,12416.45 13948.13,12416.45 13942.47,12410.79 13942.47,12405.14 13943.16,12404.45 13943.16,12398.79 13933.37,12389.06 13922.34,12378.03 13922.34,12377.96 13901.58,12357.2 13885.41,12357.2 13875.36,12347.15 13875.36,12336.29 13882.52,12329.13 13908.4,12329.13 13917.75,12319.78 13923.41,12319.78 13929.58,12325.95 13935.24,12325.95 13940.9,12320.3 13940.9,12314.64 13934.72,12308.46 13934.72,12302.81 13948.73,12288.79 13948.73,12184.82 13937.87,12173.96 13922.08,12173.96 13917.23,12169.11 13917.23,12152.51 13916.43,12151.71 13916.43,12151.11 13901.43,12136.11 U2.F2@13901.43,12125.83 ; U23.N1@13761.04,12727.82 13761.04,12727.15 v1(13775.45,12712.75)
  BOTTOM w4: v2(13367.5,12204.73) 13367.89,12205.11 v2(13398.58,12205.11) ; v1@13775.45,12715.66 v1(13775.45,12712.75) 13775.45,12697.95 13798.93,12674.47 13855.33,12674.47 13984.68,12545.12 13984.68,12482.1 14003.53,12463.26 v1(14003.53,12451.94)
DQM0: U1.E7 U2.D3 U23.N2 | length 1625.5
  TOP w4: U1.E7@13351.35,12157.32 13355.26,12153.42 13363.73,12153.42 13367.15,12156.84 13367.15,12168.58 13363.51,12172.23 13341.5,12172.23 13336.45,12177.28 13336.45,12398.1 13348.44,12410.09 13681.47,12410.09 13803.36,12531.98 13803.36,12533.06 v2(13806.47,12536.17) 13809.58,12539.29 13809.58,12541.84 13832.5,12564.76 13839.25,12564.76 13857.88,12583.39 13857.88,12607.88 13861.88,12611.88 13875.93,12611.88 13879.93,12615.88 13879.93,12623.88 13875.93,12627.88 13861.88,12627.88 13857.88,12631.88 13857.88,12644.25 13804.88,12697.26 13769.03,12697.26 13759.95,12706.33 13759.95,12706.41 13746.17,12720.2 13746.17,12744.45 U23.N2@13761.04,12759.32 ; v1(13916.72,12204.46) 13932.36,12188.82 U2.D3@13932.93,12188.82
  BOTTOM w4: v2(13806.47,12536.17) 13873.03,12469.61 13873.03,12382.88 13963.33,12292.58 13963.33,12222.55 13945.23,12204.46 v1(13916.72,12204.46)
DQM1: U1.D3 U2.E7 U23.T3 | length 1969.3
  TOP w4: U1.D3@13225.37,12188.82 13232.8,12188.82 13240.65,12196.66 v1(13244.99,12196.66) ; v1(13351.51,12323.7) 13351.76,12323.7 13372.73,12344.67 13397.75,12344.67 13409.04,12355.96 13701.39,12355.96 13928.25,12582.82 14031.35,12582.82 14038.92,12575.26 14085.4,12575.26 v1(14086.09,12574.57) 14086.45,12574.21 14086.45,12569.44 14099.65,12556.23 14104.53,12556.23 14114.57,12546.2 14114.57,12540.65 14114.57,12539.96 14122.71,12531.82 14128.36,12531.82 14129.06,12531.82 14137.2,12523.68 14137.2,12518.02 14137.2,12517.33 14145.34,12509.19 14151.68,12509.19 14175.38,12485.49 14175.38,12357.51 14159.06,12341.19 14159.06,12201.83 14147.53,12190.3 14147.53,12179.78 14142.69,12174.95 14100.3,12174.95 14098.38,12173.03 ; U23.T3@13855.53,12790.81 13872.15,12774.2 13900.34,12774.2 13925.07,12749.47 13985.87,12749.47 14062.48,12672.85 14062.48,12668.82 v1(14065.54,12665.76) ; U2.E7@14059.15,12157.33 U2.E7@14058.91,12157.33 14056.73,12159.5 14056.73,12169.19 14060.57,12173.02 14098.37,12173.02
  BOTTOM w4: v1(13244.99,12196.66) 13245.14,12196.66 13248.05,12199.57 13251.81,12199.57 13266.36,12214.12 13266.36,12239.84 13350.22,12323.7 v1(13351.51,12323.7) ; v1(14065.54,12665.76) 14064.1,12664.33 14064.1,12640.27 14083.86,12620.51 14083.86,12577.93 14086.09,12575.71 v1(14086.09,12574.57)
DQS0: U1.F3 U2.C7 U23.K2 | length 1798.7
  TOP w3.7: U1.F3@13225.37,12125.82 13225.37,12116.14 13234.68,12106.83 13241.53,12106.83 13255.36,12120.66 13255.36,12132.82 13243.43,12144.75 13243.43,12164.8 13258.84,12180.21 13258.84,12372 13214.3,12416.53 13214.3,12450.16 13258.08,12493.93 13648.64,12493.93 13746.25,12591.54 13746.25,12594.3 13737.73,12602.82 v1(13737.73,12603.5) 13737.73,12610.06 13651.83,12695.95 13651.83,12721.72 13651.83,12728.94 ; 13651.81,12728.97 13651.81,12744.57 U23.K2@13666.56,12759.32
  TOP w4: U2.C7@14058.91,12220.32 v1(14074.66,12236.06)
  BOTTOM w3.7: v1(13737.73,12603.5) 13741.56,12599.68 13745.97,12599.68 13749.51,12596.14 13791.56,12554.09 13824.12,12554.09 13892.51,12485.7 13892.51,12397.4 13999.21,12290.71 13999.21,12274.47 14010.99,12262.7 14027.13,12262.7 14037.19,12272.76 14042.42,12272.76 14046.96,12268.22 14046.96,12258.57 14058.17,12247.36 14060.98,12244.54 14064.46,12241.07 14069.47,12236.06 v1(14074.66,12236.06)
